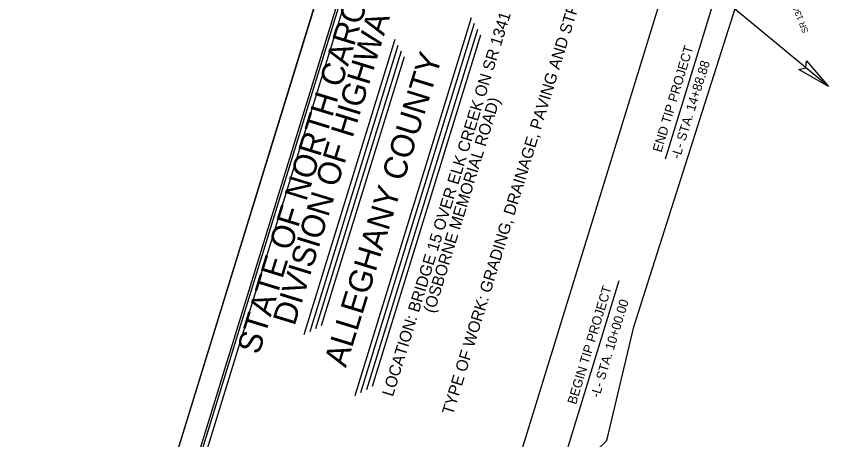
# Model space of a CAD drawing. Extents: x 1347947 to 1350662, y 1027710 to 1030532.
# Drawn here: x 1347947 to 1348821, y 1029133 to 1029589 of the extents above; entities that cross this region are included whole.
import ezdxf

# ---------------------------------------------------------------- set-up
doc = ezdxf.new("R2010")
doc.units = 0
for name, color, linetype in [('Default', 7, 'Continuous'), ('Prop Leader Line Light', 7, 'Continuous'), ('Prop Leader Line Medium', 7, 'Continuous'), ('Prop Terminator CELL', 7, 'Continuous'), ('Sheet Clip Boundary CELL', 7, 'Continuous'), ('Sheet Cutting Line CELL', 7, 'Continuous'), ('Sheet Plot Border Inside CELL', 7, 'Continuous'), ('Sheet Plot Border Outside CELL', 7, 'Continuous'), ('Sheet Title CELL', 7, 'Continuous'), ('Sheet Title Data Points CELL', 7, 'Continuous')]:
    doc.layers.add(name, color=color, linetype=linetype)

msp = doc.modelspace()

# ---------------------------------------------------------------- linework, layer by layer
at = {"layer": 'Prop Leader Line Medium'}
for p, q in [((1348700.09, 1029613.93), (1348645.14, 1029435.49)), ((1348820.98, 1029513.72), (1348700.09, 1029613.93)), ((1348535.84, 1029109.78), (1348595.87, 1029304.7))]:
    msp.add_line(p, q, dxfattribs=at)
msp.add_lwpolyline([(1348456.59, 1029010.05), (1348681.97, 1029741.89), (1349133.09, 1029602.97), (1348907.71, 1028871.13)], close=True, dxfattribs=at)
at = {"layer": 'Prop Terminator CELL'}
msp.add_lwpolyline([(1348797.35, 1029541.58), (1348820.98, 1029513.72), (1348789.11, 1029532.04), (1348796.75, 1029534)], close=True, dxfattribs=at)
at = {"layer": 'Sheet Clip Boundary CELL'}
msp.add_lwpolyline([(1348456.59, 1029010.05), (1348582.47, 1029132.61), (1348611.5, 1029255.07), (1348756.63, 1029710.8), (1349133.09, 1029602.97), (1349132.8, 1029579.86), (1349058.53, 1029368.75), (1348907.71, 1028871.13), (1348666.12, 1028948.43)], close=True, dxfattribs=at)
at = {"layer": 'Sheet Cutting Line CELL'}
msp.add_line((1347946.88, 1028557.97), (1348442.51, 1030167.38), dxfattribs=at)
at = {"layer": 'Sheet Plot Border Inside CELL'}
msp.add_lwpolyline([(1348980.53, 1028253.25), (1349471, 1029845.94), (1348462.64, 1030156.47), (1347972.16, 1028563.78)], close=True, dxfattribs=at)
at = {"layer": 'Sheet Plot Border Outside CELL'}
msp.add_lwpolyline([(1348442.51, 1030167.38), (1347946.88, 1028557.97), (1348998.14, 1028234.22), (1349493.77, 1029843.63)], close=True, dxfattribs=at)
at = {"layer": 'Sheet Title CELL'}
for p, q in [((1348311.53, 1029180.99), (1348436.92, 1029588.12)), ((1348317.78, 1029184.29), (1348440.23, 1029581.87)), ((1348324.04, 1029187.6), (1348443.52, 1029575.62)), ((1348330.28, 1029190.91), (1348446.84, 1029569.37)), ((1348256.84, 1029246.64), (1348354.77, 1029564.66)), ((1348263.08, 1029249.95), (1348358.08, 1029558.4)), ((1348269.34, 1029253.25), (1348361.38, 1029552.16)), ((1348275.59, 1029256.56), (1348364.69, 1029545.91))]:
    msp.add_line(p, q, dxfattribs=at)
for points in [[(1348458.46, 1030134.23), (1348022.85, 1028719.76)], [(1348461.76, 1030127.97), (1348043.83, 1028770.87)]]:
    msp.add_lwpolyline(points, dxfattribs=at)
at = {"layer": 'Sheet Title Data Points CELL'}
for p, q in [((1348447.72, 1029489.15), (1348447.72, 1029489.15)), ((1348360.44, 1029390.42), (1348360.44, 1029390.42))]:
    msp.add_line(p, q, dxfattribs=at)

# ---------------------------------------------------------------- texts
at = {"layer": 'Default'}
msp.add_text('SR 1341', height=6.65, rotation=111.84766, dxfattribs=at).set_placement((1348799.75, 1029573.02))
at = {"layer": 'Prop Leader Line Light'}
for s, rotation, p in [('END TIP PROJECT', 73.07402, (1348641.16, 1029442.21)), ('-L- STA. 14+88.88', 72.70897, (1348661.04, 1029435.18)), ('BEGIN TIP PROJECT', 73.07402, (1348549.36, 1029170.75)), ('-L- STA. 10+00.00', 73.07402, (1348574.34, 1029177.86))]:
    msp.add_text(s, height=10, rotation=rotation, dxfattribs=at).set_placement(p)
at = {"layer": 'Sheet Title CELL'}
for s, height, rotation, p in [('STATE OF NORTH CAROLINA', 24.9999, 72.88342, (1348208.13, 1029224.18)), ('TYPE OF WORK: GRADING, DRAINAGE, PAVING AND STRUCTURE', 12.5001, 72.88342, (1348416.76, 1029159.25)), ('DIVISION OF HIGHWAYS', 24.9999, 72.88342, (1348246.43, 1029255.18)), ('LOCATION: BRIDGE 15 OVER ELK CREEK ON SR 1341', 12.5001, 72.88342, (1348352.24, 1029179.12)), ('ALLEGHANY COUNTY', 25, 72.77365, (1348301.62, 1029210.3)), ('(OSBORNE MEMORIAL ROAD)', 12.5001, 72.88342, (1348396.65, 1029268.98))]:
    msp.add_text(s, height=height, rotation=rotation, dxfattribs=at).set_placement(p)

doc.saveas('drawing.dxf')
